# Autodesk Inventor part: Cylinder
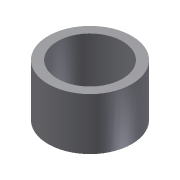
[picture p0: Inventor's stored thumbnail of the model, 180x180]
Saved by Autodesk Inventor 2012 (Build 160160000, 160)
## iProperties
Shininess: 64.0
Length Units: 11269
Angle Units: 11279
Time Units: 11290
Mass Units: 11283
Length Display Precision: 3
Angle Display Precision: 2
Compacted: True
Part Number: Cylinder
Document SubType Name: Modeling
Created: 2003-01
Designer: Owner
Density: 1 g/cm^3
Material: Default
Density: 0.0
Volumn: 0.0
Area: 0.0
PropertySet Name: Model Information
Control State: 0
Master: False
Checked Out: False
Author: Owner
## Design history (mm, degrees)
sketch "Sketch1"
  geometry: C1 r 112.5 at (0, 0); C2 r 87.5 at (0, 0)
  constraints: 2 centre point, 1 coincident, 1 concentric
  dimensions: "d0" = 225 diameter of C1; "d1" = 175 diameter of C2
extrude "Extrusion1" new body sketch "Sketch1" stored distance "d2" = 140; taper "d3" = 0 deg
body "Solid1"
